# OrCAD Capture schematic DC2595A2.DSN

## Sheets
1 PAGE1: size Custom; title: HIGH VOLTAGE DUAL STEP-DOWN DC/DC CONVERTER; rev: 2; company: TM; note: DC/DC CONVERTER with POWER SYSTEM MANAGEMENT
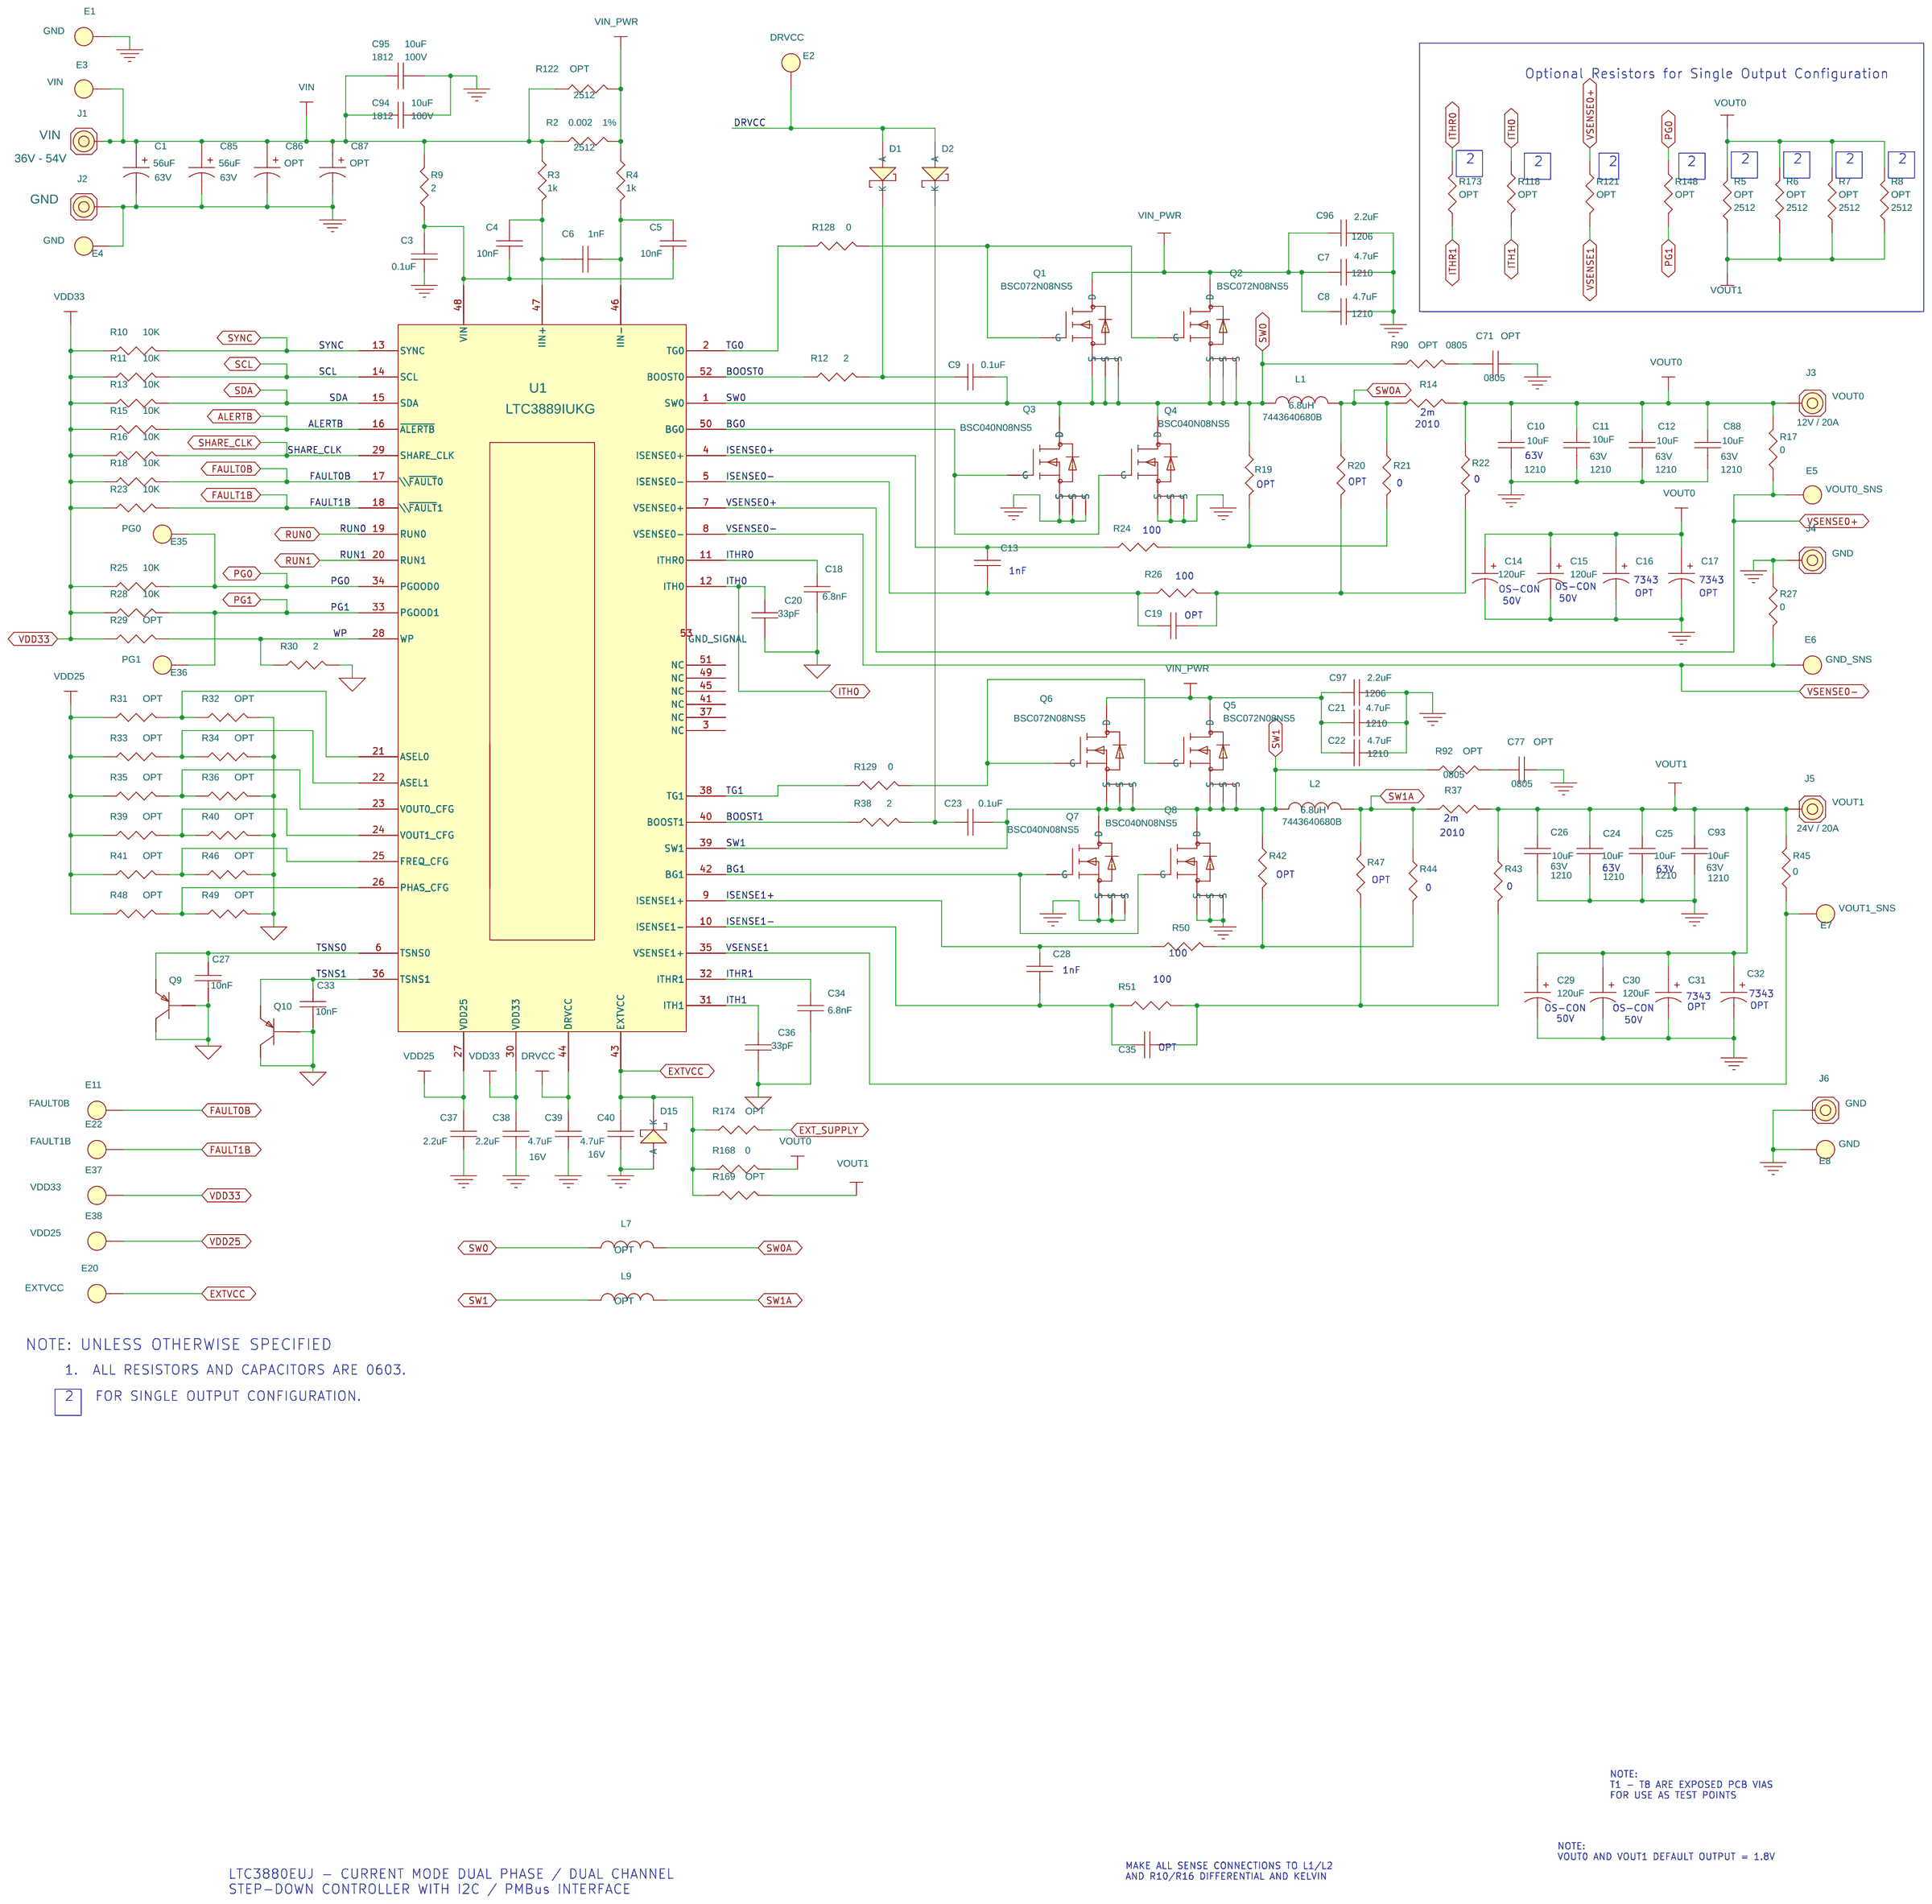
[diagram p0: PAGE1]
2 PAGE2: size Custom; note: WITH POWER SYSTEM MANAGEMENT
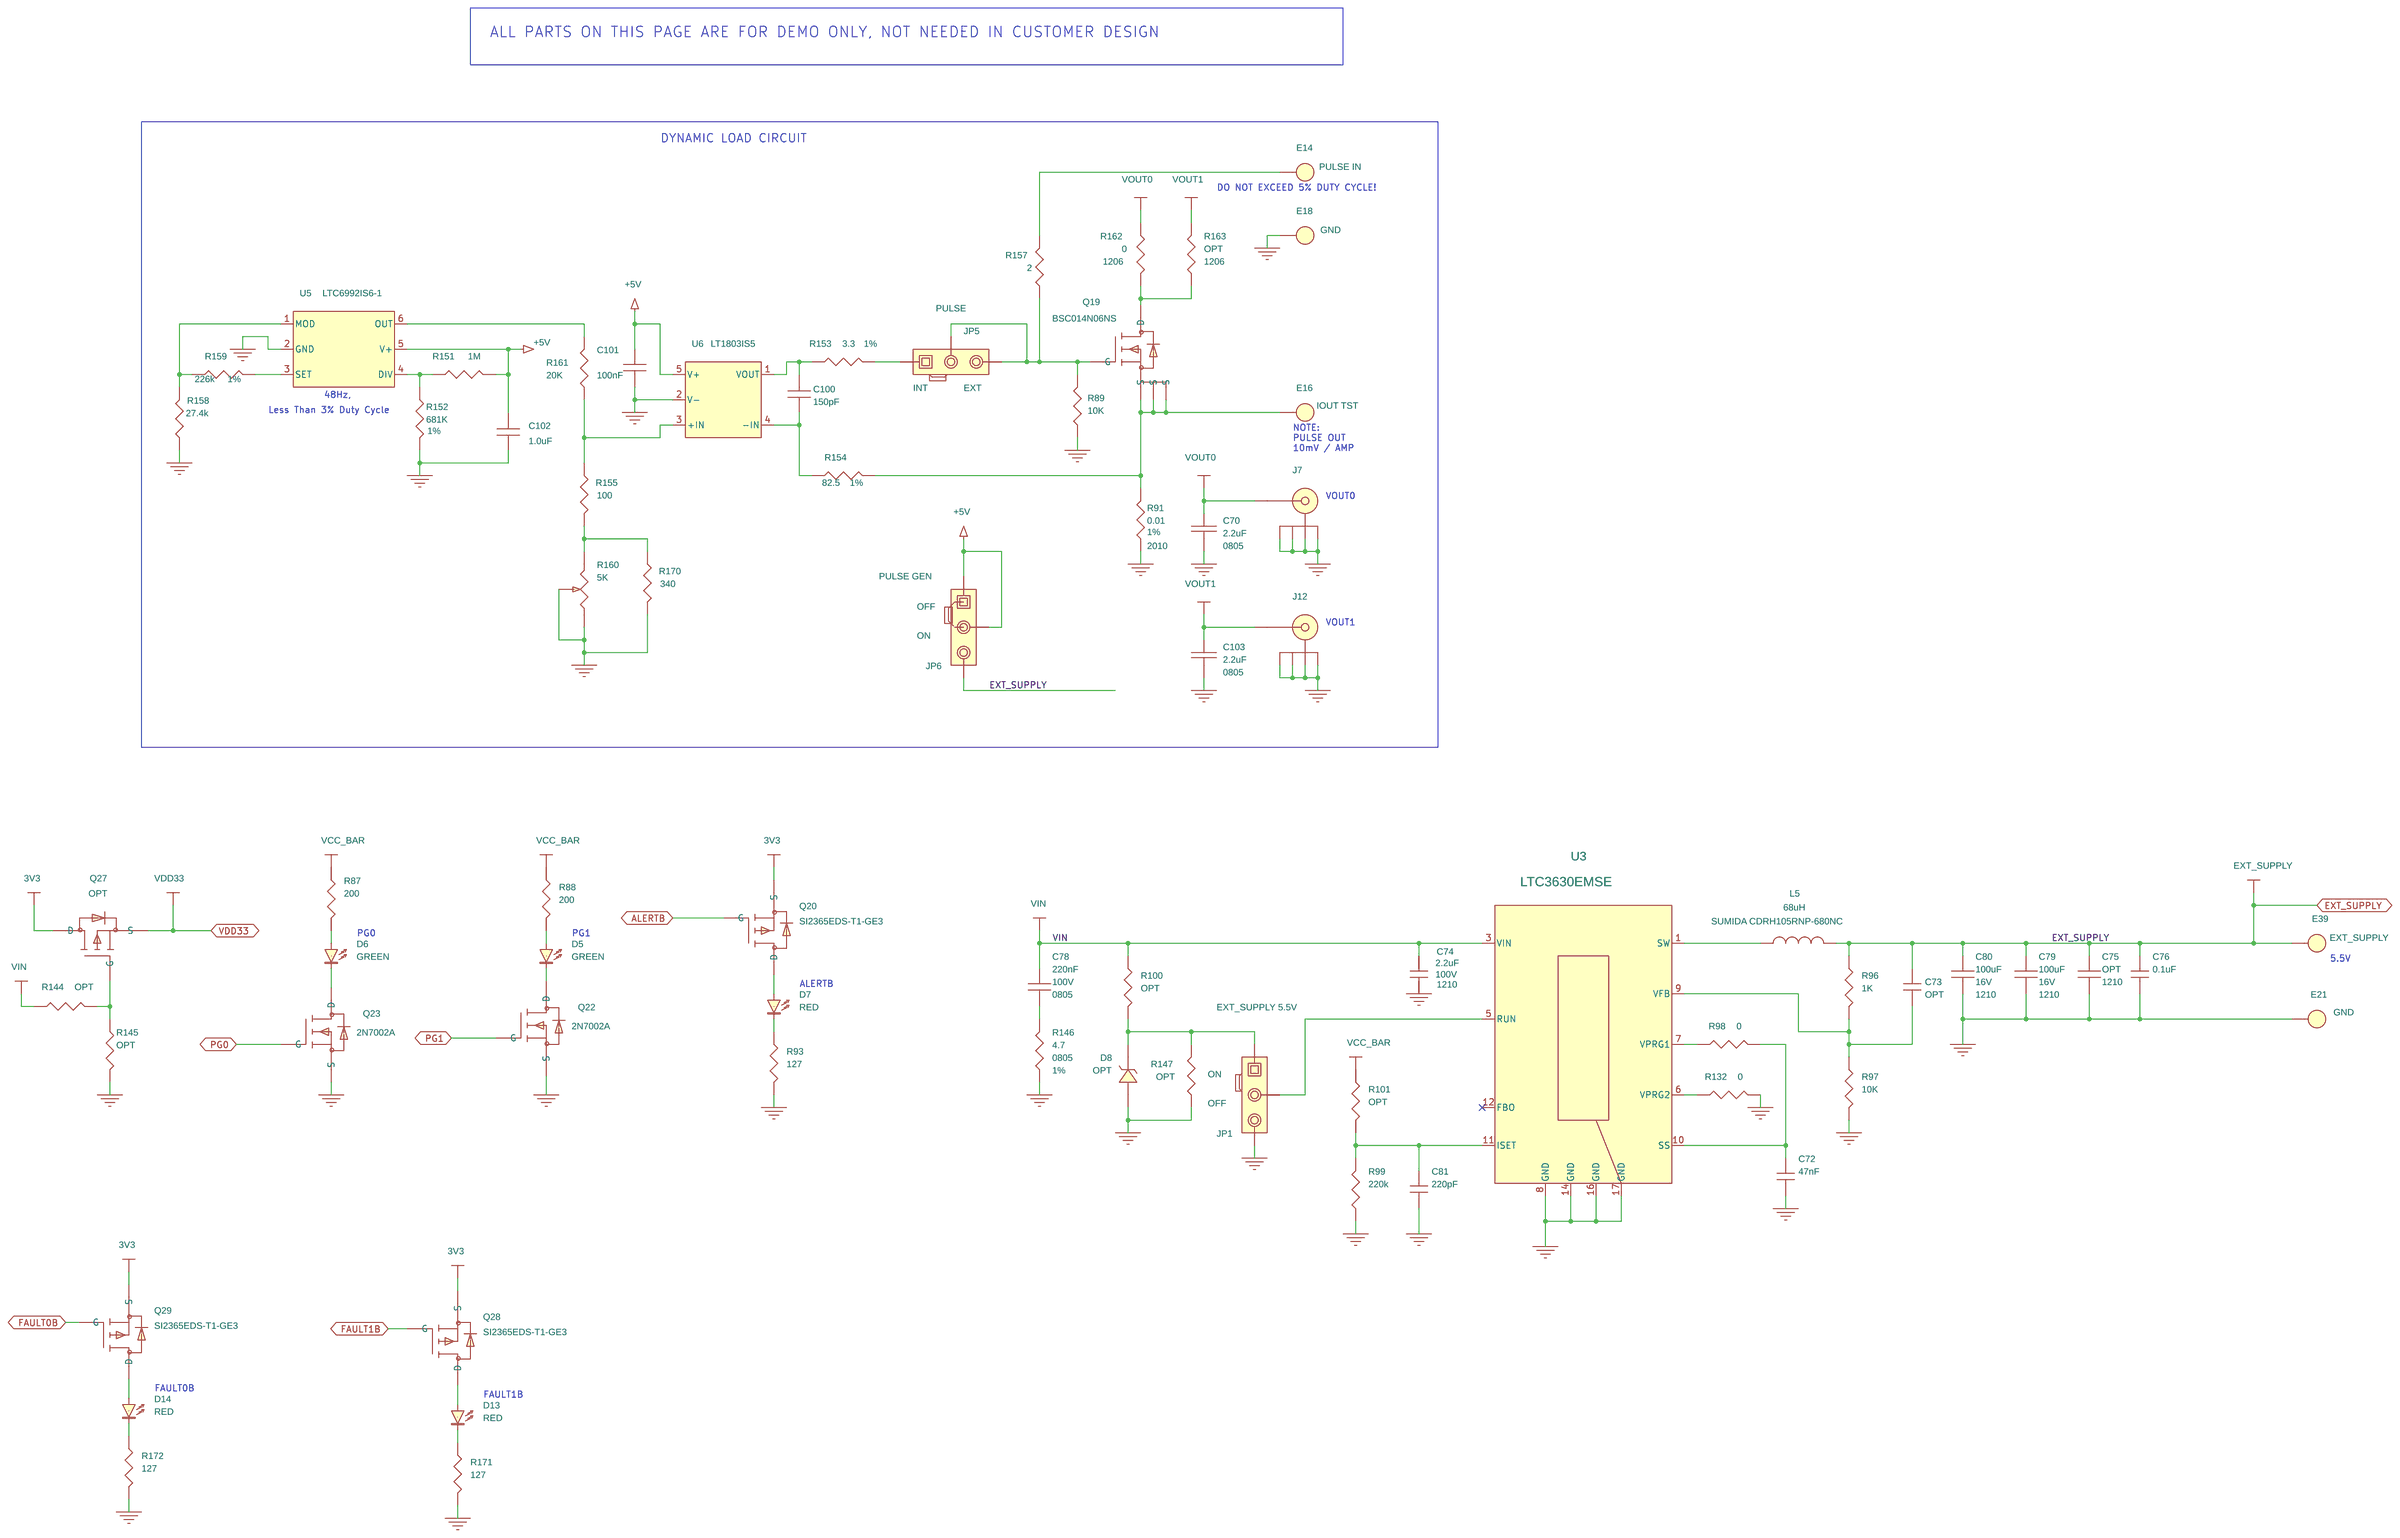
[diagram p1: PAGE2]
3 PAGE3: size B; note: WITH POWER SYSTEM MANAGEMENT
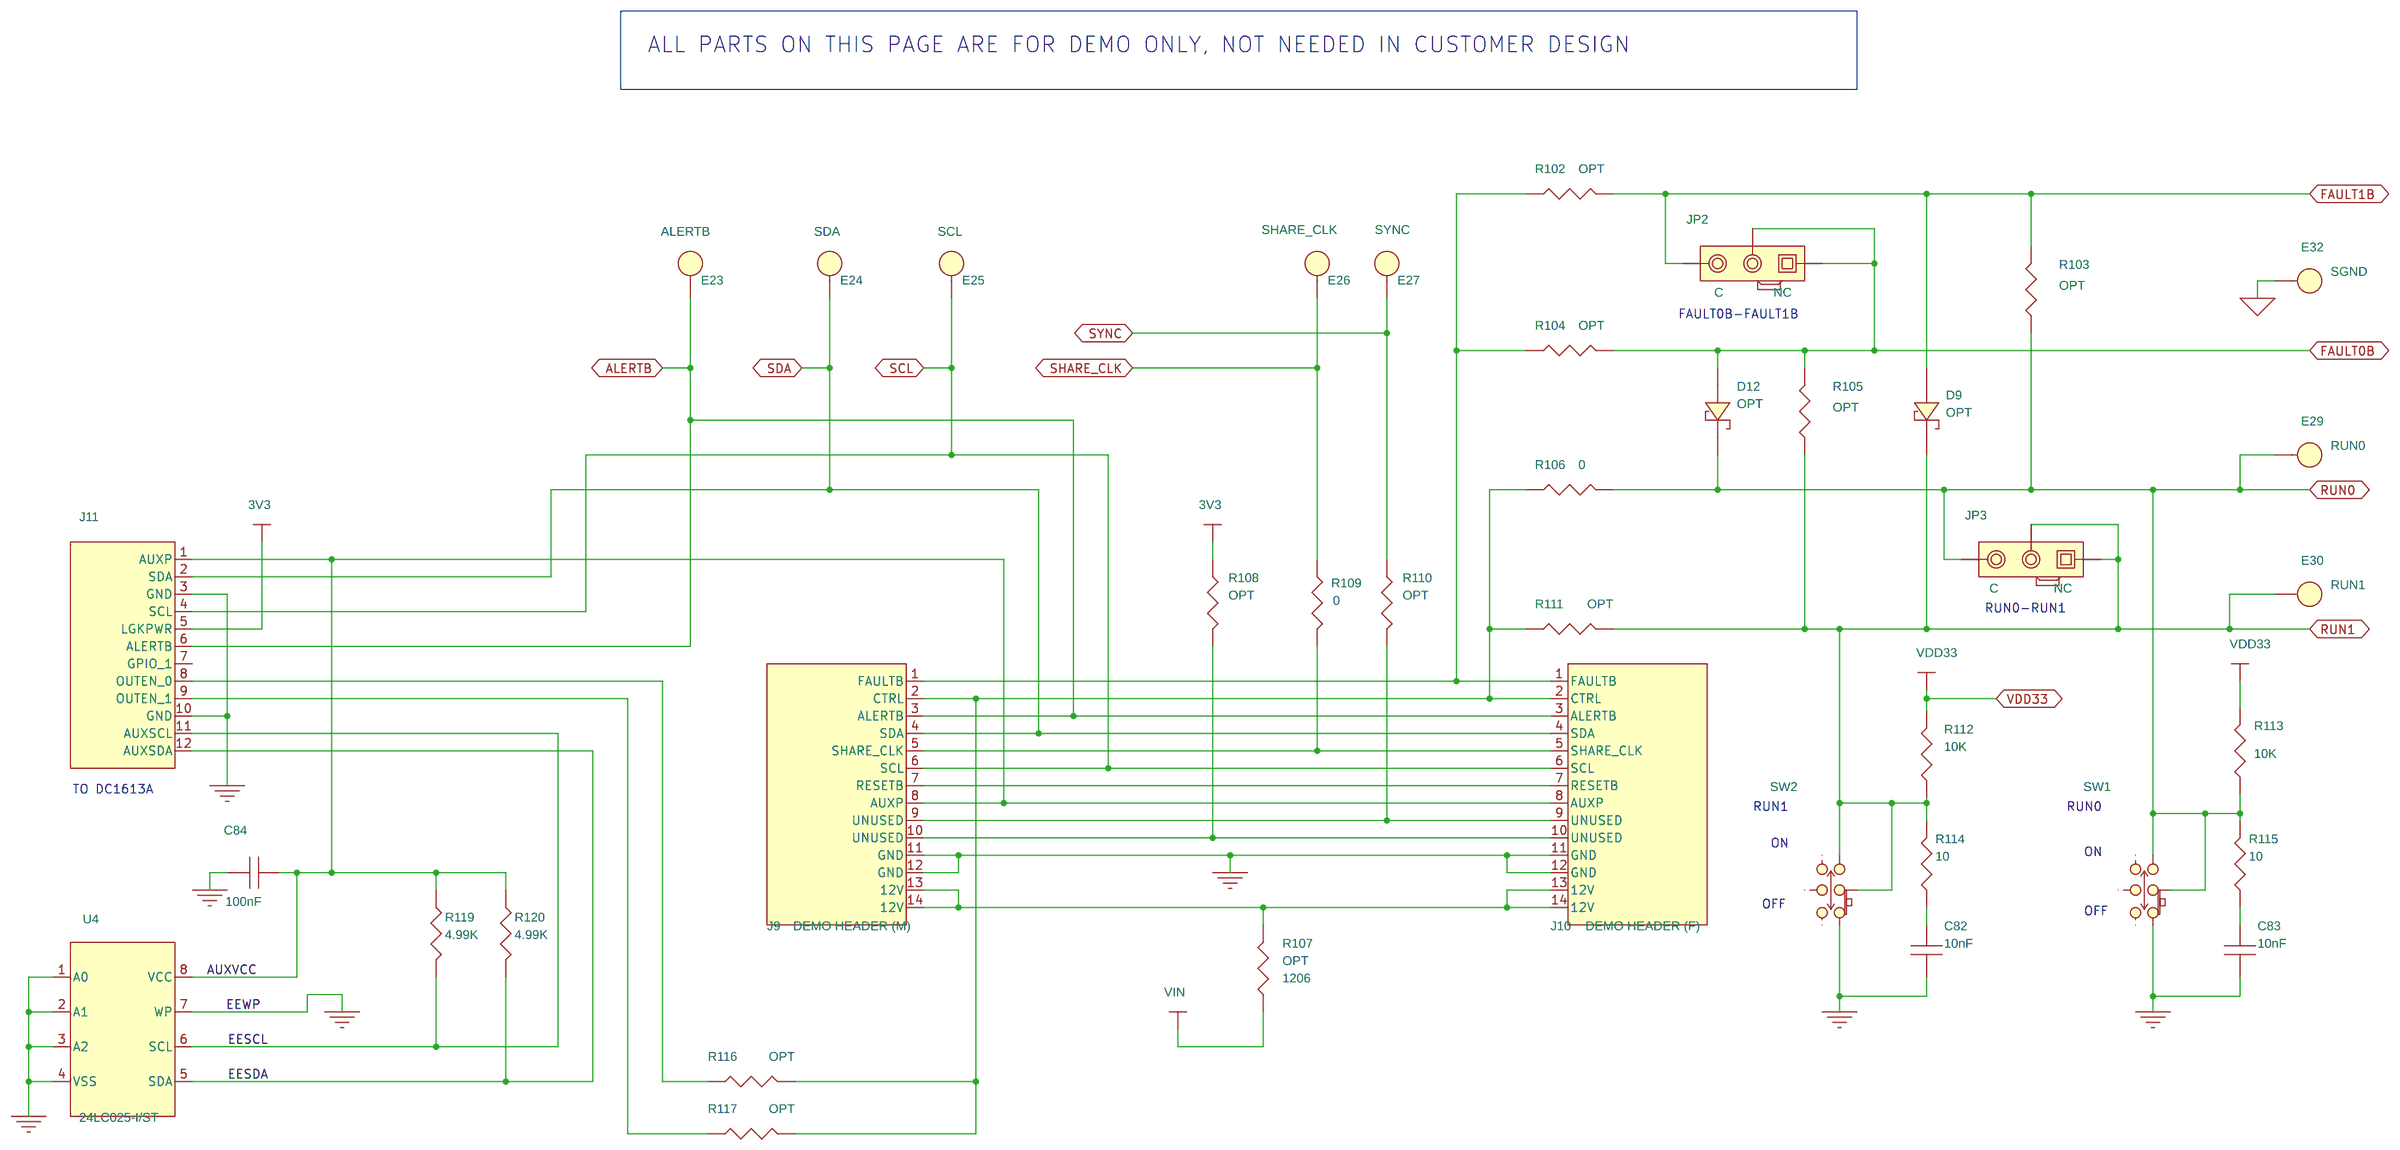
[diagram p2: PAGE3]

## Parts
sheet PAGE1
C1  56uF  [CAP\SUNCON\10X12.5]
C3  0.1uF  [0603]
C4  10nF  [0603]
C5  10nF  [0603]
C6  1nF  [0603]
C7  4.7uF  [1210]
C8  4.7uF  [1210]
C9  0.1uF  [0603]
C10  10uF  [1210]
C11  10uF  [1210]
C12  10uF  [1210]
C13  1nF  [0603]
C14  120uF  [CAP\SANYO\SVP\F8\10.3X10.3]
C15  120uF  [CAP\SANYO\SVP\F8\10.3X10.3]
C16  330uF  [7343]
C17  330uF  [7343]
C18  6.8nF  [0603]
C19  OPT  1.0uF  [0603]
C20  33pF  [0603]
C21  4.7uF  [1210]
C22  4.7uF  [1210]
C23  0.1uF  [0603]
C24  10uF  [1210]
C25  10uF  [1210]
C26  10uF  [1210]
C27  10nF  [0603]
C28  1nF  [0603]
C29  120uF  [CAP\SANYO\SVP\F8\10.3X10.3]
C30  120uF  [CAP\SANYO\SVP\F8\10.3X10.3]
C31  330uF  [7343]
C32  330uF  [7343]
C33  10nF  [0603]
C34  6.8nF  [0603]
C35  OPT 1.0uF  [0603]
C36  33pF  [0603]
C37  2.2uF  [0603]
C38  2.2uF  [0603]
C39  4.7uF  [0603]
C40  4.7uF  [0603]
C71  OPT  [0805]
C77  OPT  [0805]
C85  56uF  [CAP\SUNCON\10X12.5]
C86  OPT  [CAP\SANYO\10X10.2\CE]
C87  OPT  [CAP\SANYO\10X10.2\CE]
C88  10uF  [1210]
C93  10uF  [1210]
C94  10uF  [1812]
C95  10uF  [1812]
C96  2.2uF  [1206]
C97  2.2uF  [1206]
D1  DFLS1100-7  [POWERDI_123]
D2  DFLS1100-7  [POWERDI_123]
D15  DFLS1100-7  [POWERDI_123]
E1  PAD150-094  [PAD150-094]
E2  PAD150-094  [PAD150-094]
E3  PAD150-094  [PAD150-094]
E4  PAD150-094  [PAD150-094]
E5  PAD150-094  [PAD150-094]
E6  PAD150-094  [PAD150-094]
E7  PAD150-094  [PAD150-094]
E8  PAD150-094  [PAD150-094]
E11  PAD150-094  [PAD150-094]
E20  PAD150-094  [PAD150-094]
E22  PAD150-094  [PAD150-094]
E35  PAD150-094  [PAD150-094]
E36  PAD150-094  [PAD150-094]
E37  PAD150-094  [PAD150-094]
E38  PAD150-094  [PAD150-094]
J1  Testpin  [con\lug\10]
J2  Testpin  [con\lug\10]
J3  Testpin  [con\lug\10]
J4  Testpin  [con\lug\10]
J5  Testpin  [con\lug\10]
J6  Testpin  [con\lug\10]
L1  6.8uH  [IND\WURTH\7443630860]
L2  6.8uH  [IND\WURTH\7443630860]
L7  OPT  [IND\CLCRFT\SER2900]
L9  OPT  [IND\CLCRFT\SER2900]
Q1  BSC072N08NS5  [XSTR\INFINEON\PG-TDSON-8]
Q2  BSC072N08NS5  [XSTR\INFINEON\PG-TDSON-8]
Q3  BSC040N08NS5  [XSTR\INFINEON\PG-TDSON-8]
Q4  BSC040N08NS5  [XSTR\INFINEON\PG-TDSON-8]
Q5  BSC072N08NS5  [XSTR\INFINEON\PG-TDSON-8]
Q6  BSC072N08NS5  [XSTR\INFINEON\PG-TDSON-8]
Q7  BSC040N08NS5  [XSTR\INFINEON\PG-TDSON-8]
Q8  BSC040N08NS5  [XSTR\INFINEON\PG-TDSON-8]
Q9  MMBT3906LT1G  [SOT-323]
Q10  MMBT3906LT1G  [SOT-323]
R2  0.002  [2512]
R3  1k  [0603]
R4  1k  [0603]
R5  OPT  [2512]
R6  OPT  [2512]
R7  OPT  [2512]
R8  OPT  [2512]
R9  2  [0603]
R10  10K  [0603]
R11  10K  [0603]
R12  2  [0603]
R13  10K  [0603]
R14  0.003  [2010]
R15  10K  [0603]
R16  10K  [0603]
R17  0  [0603]
R18  10K  [0603]
R19  1.40K  [0603]
R20  0  [0603]
R21  0  [0603]
R22  0  [0603]
R23  10K  [0603]
R24  100  [0603]
R25  10K  [0603]
R26  100  [0603]
R27  0  [0603]
R28  10K  [0603]
R29  OPT  [0603]
R30  2  [0603]
R31  OPT  [0603]
R32  OPT  [0603]
R33  OPT  [0603]
R34  OPT  [0603]
R35  OPT  [0603]
R36  OPT  [0603]
R37  0.003  [2010]
R38  2  [0603]
R39  OPT  [0603]
R40  OPT  [0603]
R41  OPT  [0603]
R42  OPT 1.40K  [0603]
R43  0  [0603]
R44  0  [0603]
R45  0  [0603]
R46  OPT  [0603]
R47  OPT  0  [0603]
R48  OPT  [0603]
R49  OPT  [0603]
R50  100  [0603]
R51  100  [0603]
R90  OPT  [0805]
R92  OPT  [0805]
R118  OPT  [0603]
R121  OPT  [0603]
R122  OPT  [2512]
R128  0  [0603]
R129  0  [0603]
R148  OPT  [0603]
R168  0  [0603]
R169  OPT  [0603]
R173  OPT  [0603]
R174  OPT  [0603]
U1  LTC3889IUKG  [LT_UKG52(46)_7mmX8mm]
sheet PAGE2
C70  2.2uF  [0805]
C72  47nF  [0603]
C73  OPT  [0603]
C74  2.2uF  [1210]
C75  OPT  [1210]
C76  0.1uF  [0603]
C78  220nF  [0805]
C79  100uF  [1210]
C80  100uF  [1210]
C81  220pF  [0603]
C100  150pF  [0603]
C101  100nF  [0603]
C102  1.0uF  [0603]
C103  2.2uF  [0805]
D5  GREEN  [LED_0603]
D6  GREEN  [LED_0603]
D7  RED  [LED_0603]
D8  OPT  [SOD123]
D13  RED  [LED_0603]
D14  RED  [LED_0603]
E14  PAD150-094  [PAD150-094]
E16  PAD150-094  [PAD150-094]
E18  PAD150-094  [PAD150-094]
E21  PAD150-094  [PAD150-094]
E39  PAD150-094  [PAD150-094]
J7  XXX  [BNC5]
J12  XXX  [BNC5]
JP1  3 Pins 2mm Ctrs.  [SIP\3P\2MM]
JP5  3 Pins 2mm Ctrs.  [SIP\3P\2MM]
JP6  3 Pins 2mm Ctrs.  [SIP\3P\2MM]
L5  68uH  [IND\SUMIDA\CDRH105R\12X12]
Q19  BSC014N06NS  [LFPAK]
Q20  SI2365EDS-T1-GE3  [SOT23]
Q22  2N7002A  [SOT23]
Q23  2N7002A  [SOT23]
Q27  OPT  [SOT23]
Q28  SI2365EDS-T1-GE3  [SOT23]
Q29  SI2365EDS-T1-GE3  [SOT23]
R87  200  [0603]
R88  200  [0603]
R89  10K  [0603]
R91  0.01  [2010]
R93  127  [0603]
R96  1K  [0603]
R97  10K  [0603]
R98  0  [0603]
R99  220k  [0603]
R100  OPT  [0603]
R101  OPT  [0603]
R132  0  [0603]
R144  OPT  [0603]
R145  OPT  [0603]
R146  4.7  [0805]
R147  OPT  [0603]
R151  1M  [0603]
R152  681K  [0603]
R153  3.3  [0603]
R154  82.5  [0603]
R155  100  [0603]
R157  2  [0603]
R158  27.4k  [0603]
R159  226k  [0603]
R160  5K  [BOURNS_3386P]
R161  20K  [0603]
R162  0  [1206]
R163  OPT  [1206]
R170  340  [0603]
R171  127  [0603]
R172  127  [0603]
U3  LTC3630EMSE  [LT_MSE16_12]
U5  LTC6992IS6-1  [LT_S6]
U6  LT1803IS5  [LT_S5]
XJP1  2mm Ctrs.
XJP5  2mm Ctrs.
XJP6  2mm Ctrs.
sheet PAGE3
C82  10nF  [0603]
C83  10nF  [0603]
C84  100nF  [0603]
D9  OPT  [SOD-323]
D12  OPT  [SOD-323]
E23  ALERTB  [PAD150-094]
E24  SDA  [PAD150-094]
E25  SCL  [PAD150-094]
E26  SHARE_CLK  [PAD150-094]
E27  SYNC  [PAD150-094]
E29  RUN0  [PAD150-094]
E30  RUN1  [PAD150-094]
E32  SGND  [PAD150-094]
J9  DEMO HEADER (M)  [NPPN072FJFN]
J10  DEMO HEADER (F)  [NPPN072FJFN-RC]
J11  HD2X6-079  [HD2X6-079-MOLEX]
JP2  3 Pins 2mm Ctrs.  [SIP\3P\2MM]
JP3  3 Pins 2mm Ctrs.  [SIP\3P\2MM]
R102  OPT  [0603]
R103  OPT  [0603]
R104  OPT  [0603]
R105  OPT  [0603]
R106  0  [0603]
R107  OPT  [1206]
R108  OPT  [0603]
R109  0  [0603]
R110  OPT  [0603]
R111  OPT  [0603]
R112  10K  [0603]
R113  10K  [0603]
R114  10  [0603]
R115  10  [0603]
R116  OPT  [0603]
R117  OPT  [0603]
R119  4.99K  [0603]
R120  4.99K  [0603]
SW1  JP3X1/079\NO\12  [JS202011]
SW2  JP3X1/079\NO\12  [JS202011]
U4  24LC025-I/ST  [TSSOP-8_4.4MM]
XJP2  2mm Ctrs.
XJP3  2mm Ctrs.

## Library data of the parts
C1 C85 = CAP_POL: CAP, 56uF 20% 63V ELEC; Part Number: SUNCON 63HVP56M; VOLTAGE: 63V
C3 C9 C23 = CAP0603_1: CAP, 0603 0.1uF 10% 100V X7R; Component: cap; Manufacturer: TDK; Manufacturer P/N: C1608X7R1H104K; Part Number: MURATA GRM188R72A104KA35D; Tolerance: 10%; Type: cer 0603 X7R; Vendor: Digikey; Vendor P/N: 445-1314-1-ND
C4 C5 = CAP0603_1: CAP, 0603 10nF 10% 100V X7R; Component: cap; Manufacturer: TDK; Manufacturer P/N: C1608X7R1H104K; Part Number: MURATA GRM188R72A103KA01D; Tolerance: 10%; Type: cer 0603 X7R; Vendor: Digikey; Vendor P/N: 445-1314-1-ND
C6 = CAP0603_1: CAP, 0603 1nF 10% 100V X7R; Component: cap; Manufacturer: TDK; Manufacturer P/N: C1608X7R1H104K; Part Number: AVX 06031C102KAT2A; Tolerance: 10%; Type: cer 0603 X7R; Vendor: Digikey; Vendor P/N: 445-1314-1-ND; Volts/Amps/Watts: 50V
C7 C21 C22 = CAP1210_1: CAP, 1210 2.2uF 10% 100V X7R; Component: cap; Part Number: MURATA GRM32ER72A225KA35L; Part Type: CAP1812; Tolerance: 10%; Type: cer 1210; Vendor: Digikey; Vendor P/N: 587-1439-1-ND; Volts/Amps/Watts: 100V
C8 = CAP1210_1: CAP, 1210 2.2uF 10% 100V X7R; Component: cap; Part Number: MURATA GRM32ER72A225KA35L; Tolerance: 10%; Type: cer 1210; Vendor: Digikey; Vendor P/N: 587-1439-1-ND; Volts/Amps/Watts: 100V
C10 C25 C26 = CAP0603_1: CAP, 1210 10uF 20% 35V X5R; Component: cap; Manufacturer: Taiyo Yuden; Manufacturer P/N: GMJ325KB7106KMHT; Part Number: GMJ325KB7106KMHT; Part Type: CAP1210; Tolerance: 20%; Type: cer 1210 X5R; Vendor: Digikey; Vendor P/N: 445-1437-1-ND; Volts/Amps/Watts: 16V
C11 C12 C24 C88 C93 = CAP0603_1: CAP, 1210 10uF 20% 35V X5R; Component: cap; Manufacturer: Taiyo Yuden; Manufacturer P/N: GMJ325KB7106KMHT; Part Number: GMJ325KB7106KMHT; Part Type: CAP1210; Tolerance: 20%; Type: cer 1210 X5R; Vendor: Digikey; Vendor P/N: 445-1437-1-ND; Volts/Amps/Watts: 63V
C13 C28 = CAP0603_1: CAP, 0603 1nF 10% 16V X7R; Component: cap; Manufacturer: AVX; Manufacturer P/N: 06035C102KAT2A; Part Number: AVX 0603YC102KAT2A; Tolerance: 10%; Type: cer 0603 X7R; Vendor: Digikey; Vendor P/N: 478-1215-1-ND; Volts/Amps/Watts: 50V
C14 C29 C30 = CAPR12X5_0: CAP, 150uF 16V ELEC. OS-CON; Component: cap; Manufacturer: SANYO; Manufacturer P/N: 6TPF330M9L; Part Number: PANASONIC 35SVPF120M; Tolerance: 20%; Type: TANT; Volts/Amps/Watts: 6.3V
C15 = CAPR12X5_0: CAP, 150uF 16V ELEC. OS-CON; Component: cap; Manufacturer: SANYO; Manufacturer P/N: 6TPF330M9L; Part Number: PANASONIC 35SVPF120M; Part Type: CAP7343-43; Tolerance: 20%; Type: TANT; Volts/Amps/Watts: 6.3V
C16 C17 C31 C32 = CAPR12X5_0: CAP, 7343 OPTION; Component: cap; Manufacturer: SANYO; Manufacturer P/N: 6TPF330M9L; Part Number: OPTION; Tolerance: 20%; Type: TANT; Volts/Amps/Watts: 6.3V
C18 C34 = CAP0603_1: CAP, 0603 4.7nF 10% 50V X7R; Component: cap; Manufacturer: TDK; Manufacturer P/N: C1608C0G1H102J; Part Number: AVX 06035C472KAT2A; Tolerance: 5%; Type: cer 0603; Vendor: Digikey; Vendor P/N: 445-1293-1-ND; Volts/Amps/Watts: 50V
C19 C35 = CAP0603_1: CAP, 0603 OPTION; Manufacturer: Taiyo Yuden; Manufacturer P/N: EMK107B7105KA-T; Part Number: OPTION; Type: cer 0603 X7R; Vendor: Digikey; Vendor P/N: 587-1241-1-ND; Volts/Amps/Watts: 16V
C20 C36 = CAP0603_1: CAP, 0603 100pF 5% 50V C0G; Component: cap; Manufacturer: TDK; Manufacturer P/N: C1608C0G1H101J; Part Number: AVX 06035A101JAT2A; Tolerance: 5%; Type: cer 0603; Vendor: Digikey; Vendor P/N: 445-1281-1-ND
C27 C33 = CAP0603_1: CAP, 0603 10nF 10% 100V X7R; Component: cap; Manufacturer: TDK; Manufacturer P/N: C1608X7R1H103K; Part Number: MURATA GRM188R72A103KA01D; Tolerance: 10%; Type: cer 0603; Vendor: Digikey; Vendor P/N: 445-1311-1-ND; Volts/Amps/Watts: 50V
C37 C38 = CAP0603_1: CAP, 0603 2.2uF 10% 16V X5R; Component: cap; Manufacturer: TDK; Manufacturer P/N: C1608X7R1H104K; Part Number: AVX 0603YD225KAT2A; Tolerance: 10%; Type: cer 0603 X7R; Vendor: Digikey; Vendor P/N: 445-1314-1-ND; Volts/Amps/Watts: 50V
C39 = CAP0603_1: CAP, 0603 4.7uF 10% 16V X5R; Component: cap; Manufacturer: TDK; Manufacturer P/N: C1608X7R1H104K; Part Number: AVX 0603ZD475KAT2A; Tolerance: 10%; Type: cer 0603 X7R; Vendor: Digikey; Vendor P/N: 445-1314-1-ND; Volts/Amps/Watts: 16V
C40 = CAP0603_1: CAP, 0603 4.7uF 10% 16V X5R; Component: cap; Manufacturer: TDK; Manufacturer P/N: C1608X7R1H104K; Part Number: MURATA GRM188R61C475KAAJD; Tolerance: 10%; Type: cer 0603 X7R; Vendor: Digikey; Vendor P/N: 445-1314-1-ND; Volts/Amps/Watts: 16V
C71 C77 = CAP0603_1: CAP, 0805 OPTION; Component: cap; Manufacturer: TDK; Manufacturer P/N: C1608X7R1H104K; Part Number: OPTION; Tolerance: 10%; Type: cer 0603 X7R; Vendor: Digikey; Vendor P/N: 445-1314-1-ND; Volts/Amps/Watts: 50V
C86 C87 = CAP_POL: CAP, ELEC OPTION; Part Number: OPTION; VOLTAGE: 63V
C94 C95 = CAP1210_1: CAP, 1812 10uF 20% 100V X7S; Component: cap; Manufacturer: Taiyo Yuden; Manufacturer P/N: GMK325BJ106KN-T; Part Number: TDK CKG45NX7S2A106M500JH; Tolerance: 10%; Type: cer 1210; Vendor: Digikey; Vendor P/N: 587-1439-1-ND; Volts/Amps/Watts: 100V
C96 C97 = CAP0603_1: CAP, 1206 2.2uF 10% 100V X7R; Component: cap; Manufacturer: TDK; Manufacturer P/N: C1608X7R1H104K; Part Number: MURATA GRM31CR72A225KA73L; Tolerance: 10%; Type: cer 0603 X7R; Vendor: Digikey; Vendor P/N: 445-1314-1-ND; Volts/Amps/Watts: 100V
D1 D15 = cmdsh-3_1: DIODE, SCHOTTKY 100V, 1A; Component: diode; Manufacturer: Central; Manufacturer P/N: CMDSH-3TR; Part Number: DIODES/ZETEX, DFLS1100-7; Type: Schottky; Vendor: Mouser; Vendor P/N: 610-CMDSH-3; Volts/Amps/Watts: 30V 100mA
D2 = cmdsh-3_2: DIODE, SCHOTTKY 100V, 1A; Component: diode; Manufacturer: Central; Manufacturer P/N: CMDSH-3TR; Part Number: DIODES/ZETEX, DFLS1100-7; Type: Schottky; Vendor: Mouser; Vendor P/N: 610-CMDSH-3; Volts/Amps/Watts: 30V 100mA
E1 E4 E8 E18 = E: TURRET; 10th Part Field: 3.3V / 3A; 9th Part Field: GND; Part Number: MILL-MAX 2501-2-00-80-00-00-07-0
E2 = E: TURRET; 10th Part Field: 3.3V / 3A; 9th Part Field: DRVCC; Part Number: MILL-MAX 2501-2-00-80-00-00-07-0
E3 = E: TURRET; 10th Part Field: 3.3V / 3A; 9th Part Field: VIN; Part Number: MILL-MAX 2501-2-00-80-00-00-07-0
E5 = E: TURRET; 10th Part Field: 3.3V / 3A; 9th Part Field: VOUT0_SNS; Part Number: MILL-MAX 2501-2-00-80-00-00-07-0
E6 = E: TURRET; 10th Part Field: 3.3V / 3A; 9th Part Field: GND_SNS; Part Number: MILL-MAX 2501-2-00-80-00-00-07-0
E7 = E: TURRET; 10th Part Field: 3.3V / 3A; 9th Part Field: VOUT1_SNS; Part Number: MILL-MAX 2501-2-00-80-00-00-07-0
E11 = E: TURRET; 10th Part Field: 3.3V / 3A; 9th Part Field: FAULT0B; Part Number: MILL-MAX 2501-2-00-80-00-00-07-0
E20 = E: TURRET; 10th Part Field: 3.3V / 3A; 9th Part Field: EXTVCC; Part Number: MILL-MAX 2501-2-00-80-00-00-07-0
E22 = E: TURRET; 10th Part Field: 3.3V / 3A; 9th Part Field: FAULT1B; Part Number: MILL-MAX 2501-2-00-80-00-00-07-0
E35 = E: TURRET; 10th Part Field: 3.3V / 3A; 9th Part Field: PG0; Part Number: MILL-MAX 2501-2-00-80-00-00-07-0
E36 = E: TURRET; 10th Part Field: 3.3V / 3A; 9th Part Field: PG1; Part Number: MILL-MAX 2501-2-00-80-00-00-07-0
E37 = E: TURRET; 10th Part Field: 3.3V / 3A; 9th Part Field: VDD33; Part Number: MILL-MAX 2501-2-00-80-00-00-07-0
E38 = E: TURRET; 10th Part Field: 3.3V / 3A; 9th Part Field: VDD25; Part Number: MILL-MAX 2501-2-00-80-00-00-07-0
J1 = PEM-kfh-032-10: STUD, TESTPIN; 10th Part Field: 36V - 54V; 9th Part Field: VIN; Part Number: PEM KFH-032-10
J2 = PEM-kfh-032-10: STUD, TESTPIN; 10th Part Field: 5 - 24V #; 9th Part Field: GND; Part Number: PEM KFH-032-10
J3 = PEM-kfh-032-10: STUD, TESTPIN; 10th Part Field: 12V / 20A; 9th Part Field: VOUT0; Part Number: PEM KFH-032-10
J4 J6 = PEM-kfh-032-10: STUD, TESTPIN; 10th Part Field: 12V, MAX 10A; 9th Part Field: GND; Part Number: PEM KFH-032-10
J5 = PEM-kfh-032-10: STUD, TESTPIN; 10th Part Field: 24V / 20A; 9th Part Field: VOUT1; Part Number: PEM KFH-032-10
L1 = IND-RLF7030-OPT_1: IND, 8.6uH; Component: ind; Label: <label>; Manufacturer: VITECH; Manufacturer P/N: 7443640680B; Part Number: WURTH ELEKTRONIK 7443630860; Vendor: LTC; Vendor P/N: 59PR9875N; Volts/Amps/Watts: 20A
L2 = IND-RLF7030-OPT_0: IND, 8.6uH; Component: ind; Label: <label>; Manufacturer: VITECH; Manufacturer P/N: 7443640680B; Part Number: WURTH ELEKTRONIK 7443630860; Vendor: LTC; Vendor P/N: 59PR9875N; Volts/Amps/Watts: 20A
L7 L9 = IND-RLF7030-OPT_1: IND, 6.8uH OPTION; Component: ind; Label: <label>; Manufacturer: VITECH; Manufacturer P/N: 59PR9875N; Part Number: COILCRAFT SER2915H-682KL/SER2918H-682KL OPTION; Vendor: LTC; Vendor P/N: 59PR9875N; Volts/Amps/Watts: 20A
Q1 Q6 = MOS_FET_6: XSTR, MOSFET N-CH 60V 25A 5 PIN LFPAK; Part Number: RENESAS RJK0651DPB
Q2 Q4 Q5 Q8 = MOS_FET_6: XSTR, OPTION; Part Number: OPTION
Q3 Q7 = MOS_FET_6: XSTR, MOSFET N-CH 60V 45A 5 PIN LFPAK; Part Number: RENESAS RJK0653DPB
Q9 Q10 = MMBT3906LT1_0: XSTR, PNP GENERAL PURPOSE SOT-323; Component: trans; Part Number: DIODES INC. MMST3906-7-F; Part Type: MMBT3906LT1; Vendor P/N: MMBT3906LT1GOSCT-ND
R2 R122 = RES2512_0: RES, 2512 0.006 OHMS 1% 1W; Component: res; Manufacturer: Panasonic; Part Number: PANASONIC ERJ-M1WSF6MU; Tolerance: 1%; Volts/Amps/watts: 1W
R3 R4 = RES0603_9: RES, 0603 1k OHMS 5% 1/10W; Manufacturer: Rohm; Manufacturer P/N: MCR03EZPFX2201; Part Number: VISHAY CRCW06031K00JNEA; Vendor: Digikey; Vendor P/N: RHM2.20KHCT-ND; Volts/Amps/Watts: 0.1W
R5-R7 = RES0603_5: RES, 2512 0 OHM JUMPER OPTION; Label: 1W; Manufacturer: VISHAY; Manufacturer P/N: CRCW251230R0JNEG; Part Number: RN5326 2512 TEPRO NAKOMA OPTION; Tolerance: 5%; Vendor: Digikey; Vendor P/N: 541-30XCT-ND; Volts/Amps/Watts: 0.1W
R8 = RES0603_5: RES, 2512 0 OHM JUMPER OPTION; Label: 1W; Manufacturer: VISHAY; Manufacturer P/N: CRCW251230R0JNEG; Part Number: RN5326 2512 TEPRO NAKOMA OPTION; Tolerance: 5%; Vendor: Digikey; Vendor P/N: 541-30XCT-ND; Volts/Amps/Watts: 1W
R9 = RES0603_9: RES, 0603 2 OHMS 5% 1/10W; Manufacturer: Rohm; Manufacturer P/N: RHM0.0GCT-ND; Part Number: VISHAY CRCW06032R00JNEA; Vendor: Digikey; Vendor P/N: RHM0.0GCT-ND; Volts/Amps/Watts: 0.1W
R10 R11 R13 R15 R16 R18 R23 R25 R28 R112 R113 = RES0603_9: RES, 0603 10k OHMS 5% 1/10W; Manufacturer: Panasonic; Manufacturer P/N: ERJ-3EKF1000V; Part Number: VISHAY CRCW060310K0JNEA; Part Type: CR0402; Vendor: Digikey; Vendor P/N: P100HCT-ND; Volts/Amps/Watts: 0.1W
R12 R30 R38 = RES0603_9: RES, 0603 2 OHMS 5% 1/10W; Manufacturer: Panasonic; Manufacturer P/N: ERJ-3EKF1000V; Part Number: VISHAY CRCW06032R00JNEA; Part Type: CR0402; Vendor: Digikey; Vendor P/N: P100HCT-ND; Volts/Amps/Watts: 0.1W
R14 = RES2512_0: RES, 2010 3m OHMS 1% 1/2W; Component: res; Manufacturer: Panasonic; Manufacturer P/N: ERJ-M1WSF8M0U; Part Number: VISHAY WSL20103L000FEA; Tolerance: 1%; Vendor: Digikey; Vendor P/N: ERJ-M1WTF2M0U; Volts/Amps/watts: 1W
R17 = RES0603_9: RES, 0603 0 OHMS JUMPER; Manufacturer: Rohm; Manufacturer P/N: MCR03EZPFX1000; Part Number: VISHAY CRCW06030000Z0EA; Vendor: Digikey; Vendor P/N: RHM100HCT-ND; Volts/Amps/Watts: 0.1W
R19 R42 = RES0603_9: RES, 0603 OPTION; Manufacturer: Rohm; Manufacturer P/N: MCR03EZPFX2201; Part Number: OPTION; Vendor: Digikey; Vendor P/N: RHM2.20KHCT-ND; Volts/Amps/Watts: 0.1W
R20 = RES0603_9: RES, 0603 OPTION; Manufacturer: Rohm; Manufacturer P/N: RHM0.0GCT-ND; Part Number: OPTION; Tolerance: 5%; Vendor: Digikey; Vendor P/N: RHM0.0GCT-ND; Volts/Amps/Watts: 0.1W
R21 R22 R43 R44 R128 R129 = RES0603_9: RES, 0603 0 OHMS JUMPER; Manufacturer: Rohm; Manufacturer P/N: MCR03EZPFX2201; Part Number: VISHAY CRCW06030000Z0EA; Vendor: Digikey; Vendor P/N: RHM2.20KHCT-ND; Volts/Amps/Watts: 0.1W
R24 R26 = RES0603_9: RES, 0603 100 OHMS 5% 1/10W; Manufacturer: Panasonic; Manufacturer P/N: ERJ-3EKF1000V; Part Number: VISHAY CRCW0603100RJNEA; Vendor: Digikey; Vendor P/N: P100HCT-ND; Volts/Amps/Watts: 0.1W
R27 = RES0603_9: RES, 0603 0 OHMS JUMPER; Manufacturer: Yageo; Manufacturer P/N: RC0603JR-070RL; Part Number: VISHAY CRCW06030000Z0EA; Tolerance: 5%; Vendor: Digikey; Vendor P/N: 311-0.0GRCT-ND; Volts/Amps/Watts: 0.1W
R29 R31-R36 R39-R41 R46 R48 R49 R169 = RES0603_9: RES, 0603 OPTION; Manufacturer: Panasonic; Manufacturer P/N: ERJ-3EKF1000V; Part Number: OPTION; Part Type: CR0402; Vendor: Digikey; Vendor P/N: P100HCT-ND; Volts/Amps/Watts: 0.1W
R37 = RES2512_0: RES, 2010 3m OHMS 1% 1/2W; Component: res; Manufacturer: Panasonic; Manufacturer P/N: ERJ-M1WSF8M0U; Part Number: VISHAY WSL20103L000FEA; Part Type: RES2512; Tolerance: 1%; Vendor: Digikey; Vendor P/N: ERJ-M1WTF2M0U; Volts/Amps/watts: 1W
R45 = RES0603_9: RES, 0603 0 OHMS JUMPER; Manufacturer: Rohm; Manufacturer P/N: RHM0.0GCT-ND; Part Number: VISHAY CRCW06030000Z0EA; Tolerance: 5%; Vendor: Digikey; Vendor P/N: RHM0.0GCT-ND; Volts/Amps/Watts: 0.1W
R47 = RES0603_8: RES, 0603 OPTION; Manufacturer: Rohm; Manufacturer P/N: RHM0.0GCT-ND; Part Number: OPTION; Tolerance: 5%; Vendor: Digikey; Vendor P/N: RHM0.0GCT-ND; Volts/Amps/Watts: 0.1W
R50 R51 = RES0603_9: RES, 0603 100 OHMS 5% 1/10W; Component: res; Manufacturer: Panasonic; Manufacturer P/N: ERJ-3EKF1000V; Part Number: VISHAY CRCW0603100RJNEA; Tolerance: 1%; Vendor: Digikey; Vendor P/N: P100HCT-ND; Volts/Amps/Watts: 0.1W
R90 R92 = RES0603_9: RES, 0805 OPTION; Label: OPT 0; Manufacturer: Rohm; Manufacturer P/N: RHM0.0GCT-ND; Part Number: OPTION; Vendor: Digikey
R118 R121 R148 R173 = RES0603_9: RES, 0603 OPTION; Label: 0; Manufacturer: Rohm; Manufacturer P/N: MCR03EZPFX2201; Part Number: OPTION; Vendor: Digikey; Vendor P/N: RHM2.20KHCT-ND; Volts/Amps/Watts: 0.1W
R168 = RES0603_9: RES, 0603 0 OHMS JUMPER; Manufacturer: Panasonic; Manufacturer P/N: ERJ-3EKF1000V; Part Number: VISHAY CRCW06030000Z0EA; Part Type: CR0402; Vendor: Digikey; Vendor P/N: P100HCT-ND; Volts/Amps/Watts: 0.1W
R98 R174 = RES0603_9: RES, 0603 0 OHMS JUMPER; Manufacturer: ROHM; Manufacturer P/N: MCR03EZPFX4991; Part Number: VISHAY CRCW06030000Z0EA; Volts/Amps/Watts: <Volts/Amps/Watts>
U1 = LTC3880-M0001_20: ASSY, IC, WIDE INPUT AND OUTPUT DC/DC CONVERTER; Component: IC; Manufacturer: LTC; Manufacturer P/N: LTC3886IUKG; Part Number: LINEAS TECH. LTC3886IUKG#10E2-1PBF-ES; Part Type: LTC3886IUKG; Vendor: LTC; Vendor P/N: LTC3880_M0001
C70 C103 = CAP1206_1: CAP, 0805 2.2uF 10% 16V X7R; Manufacturer: Kemet; Part Number: AVX 0805YC225KAT2A; Tolerance: 10%; Type: cer 1206 X7R; Vendor: Digikey; Vendor P/N: 399-4937-1-ND; Volts/Amps/Watts: 16V
C72 = CAP-NP: CAP, 0603 47nF 10% 25V X7R; Part Number: AVX 06033C473KAT2A
C73 = CAP-NP: CAP, 0603 OPTION; Part Number: OPTION
C74 = CAP-NP: CAP, 1210 2.2uF 10% 100V X7R; 1ST PART FIELD: 100V; Part Number: MURATA GRM32ER72A225KA35L
C75 = UMK325BJ105MH: CAP, 1210 OPTION; 1st Part Field: 10V; Part Number: OPTION
C76 = CAP-NP: CAP, 0603 0.1uF 10% 25V X7R; 1ST PART FIELD: 10V; Part Number: AVX 06033C104KAT2A
C78 = UMK325BJ105MH: CAP, 0805 220nF 10% 100V X7R; 1st Part Field: 100V; Part Number: MURATA GRM21AR72A224KAC5L
C79 C80 = UMK325BJ105MH: CAP, 1210 100uF 20% 10V X5R; 1st Part Field: 16V; Part Number: MURATA GRM32ER61A107ME20L
C81 = CAP-NP: CAP, 0603 220pF 10% 50V X7R; Part Number: AVX 06035C221KAT2A
C100 = CAP_NP: CAP, 0603 150pF 5% 50V NPO; Part Number: AVX 06035A151JAT2A
C84 C101 = CAP_NP: CAP, 0603 100nF 20% 16V X7R; Part Number: AVX 0603YC104MAT2A
C102 = CAP_NP: CAP, 0603 1uF 20% 25V X5R; Part Number: AVX 06033D105MAT2A
D5 D6 = DIODE-LED_2: LED, 0603 GREEN; Label: RED; Manufacturer: PANASONIC; Part Number: OSRAM LG L29K-G2J1-24-Z
D7 D13 D14 = DIODE-LED_2: LED, 0603 RED; Manufacturer: PANASONIC; Part Number: OSRAM LS L29K-H1J2-1-Z
D8 = DIODE_ZENER31_0: DIODE, ZENER OPTION; Part Number: OPTION
E14 = E: TURRET; 10th Part Field: 3.3V / 3A; 9th Part Field: PULSE IN; Part Number: MILL-MAX 2501-2-00-80-00-00-07-0
E16 = E: TURRET; 10th Part Field: 3.3V / 3A; 9th Part Field: IOUT TST; Part Number: MILL-MAX 2501-2-00-80-00-00-07-0
E21 = E: TURRET; 9th Part Field: GND; Part Number: MILL-MAX 2501-2-00-80-00-00-07-0
E39 = E: TURRET; 10th Part Field: 3.3V / 3A; 9th Part Field: EXT_SUPPLY; Part Number: MILL-MAX 2501-2-00-80-00-00-07-0
J7 J12 = BNC5-SCH_0: CONN, BNC,5 PINS; Part Number: CONNEX 112404
JP1 = Samtec_TMM-103-02-L-S_0: HEADER, 3 PIN 2mm; 10th Part Field: ITH; 11th Part Field: OFF; 12th Part Field: EXT_SUPPLY 5.5V; 9th Part Field: ON; Part Number: SULLINS NRPN031PAEN-RC
JP5 = Samtec_TMM-103-02-L-S_0: HEADER, 3 PIN 2mm; 10th Part Field: ITH; 11th Part Field: EXT; 12th Part Field: PULSE; 9th Part Field: INT; Part Number: SULLINS NRPN031PAEN-RC
JP6 = Samtec_TMM-103-02-L-S_0: HEADER, 3 PIN 2mm; 10th Part Field: ITH; 11th Part Field: ON; 12th Part Field: PULSE GEN; 9th Part Field: OFF; Part Number: SULLINS NRPN031PAEN-RC
L5 = IND: IND, 68uH; 5th Part Field: SUMIDA CDRH105RNP-680NC; Part Number: SUMIDA CDRH105RNP-680NC
Q19 = MOS_FET_6: XSTR, MOSFET N-CH 30V 30A 5 PIN LFPAK; Part Number: RENESAS RJK0305DPB-00#J0
Q20 Q28 Q29 = P-MOSFET: XSTR, MOSFET P-CH 20V 5.2A SOT-23; Part Number: VISHAY SI2365EDS-T1-GE3
Q22 = TRANSISTOR_1: XSTR, MOSFET N-CH 60V 115mA SOT23; Part Number: FAIRCHILD 2N7002A
Q23 = TRANSISTOR_0: XSTR, MOSFET N-CH 60V 115mA SOT23; Part Number: FAIRCHILD 2N7002A
Q27 = P-MOSFET: XSTR, N-CHANNEL DMOS FET OPTION; Part Number: OPTION
R87 R88 = RES0603_9: RES, 0603 200 OHMS 5% 1/10W; Label: OPT 0; Manufacturer: Rohm; Manufacturer P/N: RHM0.0GCT-ND; Part Number: VISHAY CRCW0603200RJNEA; Tolerance: 5%; Vendor: Digikey; Vendor P/N: RHM0.0GCT-ND; Volts/Amps/Watts: 0.1W
R89 = RES0603_9: RES, 0603 10k OHMS 5% 1/10W; Part Number: VISHAY CRCW060310K0JNEA
R91 = RES0603_5: RES, 2010 0.01 OHMS 1% 1/2W; Label: 1W; Manufacturer: VISHAY; Manufacturer P/N: CRCW251230R0JNEG; Part Number: VISHAY WSL2010R0100FEA; Tolerance: 1%; Vendor: Digikey; Vendor P/N: 541-30XCT-ND; Volts/Amps/Watts: 0.1W
R93 R171 R172 = RES0603_9: RES, 0603 127 OHMS 1% 1/10W; Label: OPT 0; Manufacturer: Rohm; Manufacturer P/N: RHM0.0GCT-ND; Part Number: VISHAY CRCW0603127RFKEA; Tolerance: 5%; Vendor: Digikey; Vendor P/N: RHM0.0GCT-ND; Volts/Amps/Watts: 0.1W
R96 = RES0603_9: RES, 0603 0 OHMS JUMPER; Manufacturer: ROHM; Manufacturer P/N: MCR03EZPFX4991; Part Number: VISHAY CRCW06030000Z0EA
R97 R100 R101 R147 = RES0603_9: RES, 0603 OPTION; Manufacturer: ROHM; Manufacturer P/N: MCR03EZPFX4991; Part Number: OPTION
R99 = RES0603_9: RES, 0603 220k OHMS 5% 1/10W; Manufacturer: ROHM; Manufacturer P/N: MCR03EZPFX4991; Part Number: VISHAY CRCW0603220KJNEA
R132 = RES0603_9: RES, 0603 0 OHMS JUMPER; Manufacturer: Rohm; Manufacturer P/N: MCR03EZPFX2201; Part Number: VISHAY CRCW06030000Z0EA
R144 R145 = RES0603_11: RES, 0603 OPTION; Part Number: OPTION
R146 = RES0603_9: RES, 0805 4.7 OHMS 1% 0.125W; Label: OPT 0; Manufacturer: Rohm; Manufacturer P/N: RHM0.0GCT-ND; Part Number: VISHAY CRCW08054R70FKEA; Tolerance: 1%; Vendor: Digikey
R151 = RES0603_0: RES, 0603 1M OHMS 5% 1/10W; Label: OPT 0; Manufacturer: Rohm; Manufacturer P/N: RHM0.0GCT-ND; Part Number: VISHAY CRCW06031M00JNEA; Vendor: Digikey
R152 = RES0603_0: RES, 0603 681K OHMS 1% 1/10W; Manufacturer: ROHM; Manufacturer P/N: MCR03EZPFX4991; Part Number: VISHAY CRCW0603681KFKEA; Tolerance: 1%
R153 = RES0603_0: RES, 0603 3.3 OHMS 1% 1/10W; Manufacturer: ROHM; Manufacturer P/N: MCR03EZPFX4991; Part Number: VISHAY CRCW06033R30FKEA; Tolerance: 1%; Vendor: Digikey
R154 = RES0603_0: RES, 0603 82.5 OHMS 1% 1/10W; Manufacturer: ROHM; Manufacturer P/N: MCR03EZPFX4991; Part Number: VISHAY CRCW060382R5FKEA; Tolerance: 1%; Vendor: Digikey
R155 = RES0603_0: RES, 0603 100 OHMS 5% 1/10W; Manufacturer: ROHM; Manufacturer P/N: MCR03EZPFX4991; Part Number: VISHAY CRCW0603100RJNEA; Vendor: Digikey; Vendor P/N: RHM4.99KHCT-ND; Volts/Amps/Watts: 0.1w
R157 = RES0603_0: RES, 0603 2 OHMS 5% 1/10W; Manufacturer: ROHM; Manufacturer P/N: MCR03EZPFX4991; Part Number: VISHAY CRCW06032R00JNEA; Vendor: Digikey; Vendor P/N: RHM4.99KHCT-ND; Volts/Amps/Watts: 0.1w
R158 = RES0603_0: RES, 0603 27.4k OHMS 1% 1/10W; Manufacturer: Panasonic; Manufacturer P/N: ERJ-3EKF2002V; Part Number: VISHAY CRCW060327K4FKEA; Vendor: Digikey; Vendor P/N: P20.0KHCT-ND; Volts/Amps/Watts: 0.1W
R159 = RES0603_0: RES, 0603 226K OHMS 1% 1/10W; Component: res; Label: <label>; Manufacturer: Panasonic; Manufacturer P/N: ERJ-3EKF5901V; Part Number: VISHAY CRCW0603226KFKEA; Tolerance: 1%; Vendor: Digikey; Vendor P/N: P5.90KHCT-ND; Volts/Amps/Watts: 0.1W
R160 = POT: RES, VARIABLE 5K; Part Number: BOURNS 3386P-1-502-LF
R161 = RES0603_0: RES, 0603 20K OHMS 5% 1/10W; Manufacturer: Panasonic; Manufacturer P/N: ERJ-3EKF2002V; Part Number: VISHAY CRCW060320K0JNEA; Vendor: Digikey; Vendor P/N: P20.0KHCT-ND; Volts/Amps/Watts: 0.1W
R162 = RES2512_0: RES, 1206 0 OHMS JUMPER; Component: res; Manufacturer: Panasonic; Manufacturer P/N: ERJ-M1WSF8M0U; Part Number: VISHAY CRCW12060000Z0EA; Tolerance: 1%; Vendor: Digikey; Vendor P/N: ERJ-M1WTF2M0U; Volts/Amps/watts: 1W
R163 = RES2512_0: RES, 1206 0 OHMS JUMPER OPTION; Component: res; Manufacturer: Panasonic; Manufacturer P/N: ERJ-M1WSF8M0U; Part Number: VISHAY CRCW12060000Z0EA OPTION; Tolerance: 1%; Vendor: Digikey; Vendor P/N: ERJ-M1WTF2M0U; Volts/Amps/watts: 1W
R170 = RES0603_0: RES, 0603 340 OHMS 1% 1/10W; Manufacturer: ROHM; Manufacturer P/N: MCR03EZPFX4991; Part Number: VISHAY CRCW0603340RFKEA; Vendor: Digikey; Vendor P/N: RHM4.99KHCT-ND; Volts/Amps/Watts: 0.1w
U3 = LT3685EMSE_0: IC, SYNCHRONUS STEP-DOWN CONVERTER; Part Number: LINEAR TECH. LTC3630EMSE#PBF
U5 = LT1129CS8-3_1.3: IC, LTC6992; Part Number: LINEAR TECH. LTC6992IS6-1
U6 = LT1129CS8-3_2.3: IC, SINGLE OP AMP; Part Number: LINEAR TECH. LT1803IS5
XJP1-XJP3 XJP5 XJP6 = Samtec_2SN-BK-G_5: SHUNT; Part Number: SAMTEC 2SN-BK-G
C82 C83 = CAP_NP: CAP, 0603 10nF 10% 25V X7R; Part Number: AVX 06033C103KAT2A
D9 D12 = DIODE_SCHOTTKY_9: DIODE, OPTION; Part Number: OPTION
E23-E27 E29 E30 E32 = E_0: TURRET; Part Number: MILL-MAX 2501-2-00-80-00-00-07-0
J9 = PMBUS_HEADER20_3: HEADER, 14PIN DUAL ROW R/A; Component: con; Manufacturer: Mill Max; Manufacturer P/N: 802-40-020-20-0001; Part Number: MOLEX 87760-1416; Part Type: HDR_2X10_RA_REV; Type: header RA 20 dual row; Vendor: LTC; Vendor P/N: 802-40-020-20-001
J10 = PMBUS_CONNECTOR20_3: CONN, SOCKET 14PIN  DUAL ROW R/A; Component: con; Manufacturer: Mill Max; Manufacturer P/N: 803-93-020-20-001; Part Number: SULLINSINC. NPPN072FJFN-RC; Part Type: HDR2X10RA; Type: conn  RA 20 dual row; Vendor: LTC; Vendor P/N: 803-93-020-20-001
J11 = HD2X6-079-PMBUS_2: HEADER, 12PIN 2mm STR DL; Label: DC1427A HEADER; Manufacturer: MOLEX; Manufacturer P/N: 87831-1220; Part Number: FCI 98414-G06-12ULF; Type: header 12POS 2MM VERT; Vendor: Digikey; Vendor P/N: WM18561-ND
JP2 JP3 = Samtec_TMM-103-02-L-S_0: HEADER, 3 PIN 2mm; 10th Part Field: ITH; 11th Part Field: C; 12th Part Field: RUN1; 9th Part Field: NC; Part Number: SULLINS NRPN031PAEN-RC
R102-R105 R108 R110 R111 R117 = RES0603_0: RES, 0603 OPTION; Label: OPT 0; Manufacturer: Rohm; Manufacturer P/N: RHM0.0GCT-ND; Part Number: OPTION; Tolerance: 5%; Vendor: Digikey; Vendor P/N: RHM0.0GCT-ND; Volts/Amps/Watts: 0.1W
R106 = RES0603_0: RES, 0603 0 OHMS JUMPER; Label: OPT 0; Manufacturer: Rohm; Manufacturer P/N: RHM0.0GCT-ND; Part Number: VISHAY CRCW06030000Z0EA; Tolerance: 5%; Vendor: Digikey; Vendor P/N: RHM0.0GCT-ND; Volts/Amps/Watts: 0.1W
R107 = RES0603_3: RES, 1206 OPTION; Label: OPT 0; Manufacturer: Rohm; Manufacturer P/N: RHM0.0GCT-ND; Part Number: OPTION; Tolerance: 5%; Vendor: Digikey; Vendor P/N: RHM0.0GCT-ND; Volts/Amps/Watts: 0.1W
R109 = RES0603_0: RES, 0603 0 OHMS JUMPER; Manufacturer: Rohm; Manufacturer P/N: RHM0.0GCT-ND; Part Number: VISHAY CRCW06030000Z0EA; Tolerance: 5%; Vendor: Digikey; Vendor P/N: RHM0.0GCT-ND; Volts/Amps/Watts: 0.1W
R114 R115 = RES0603_1: RES, 0603 10 OHMS 5% 1/10W; Manufacturer: Rohm; Manufacturer P/N: RHM0.0GCT-ND; Part Number: VISHAY CRCW060310R0JNEA; Tolerance: 5%; Vendor: Digikey; Vendor P/N: RHM0.0GCT-ND; Volts/Amps/Watts: 0.1W
R116 = RES0603_3: RES, 0603 OPTION; Label: OPT 0; Manufacturer: Rohm; Manufacturer P/N: RHM0.0GCT-ND; Part Number: OPTION; Tolerance: 5%; Vendor: Digikey; Vendor P/N: RHM0.0GCT-ND; Volts/Amps/Watts: 0.1W
R119 R120 = RES0603_0: RES, 0603 4.99K OHMS 1% 1/10W; Manufacturer: ROHM; Manufacturer P/N: MCR03EZPFX4991; Part Number: VISHAY CRCW06034K99FKEA; Vendor: Digikey; Vendor P/N: RHM4.99KHCT-ND; Volts/Amps/Watts: 0.1w
SW1 SW2 = JP3X1_079_NO_12_3: SWITCH, SUBMINATURE SLIDE; Part Number: C&K JS202011CQN
U4 = 24LC025-I_SN: IC, 24LC05-I/ST; Part Number: MICROCHIP 24LC025-I/ST

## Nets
3V3: J11.5(LGKPWR) Q20.2(S) Q27.3(D) Q28.2(S) Q29.2(S) R87.1 R88.1 R108.1
+5V: C101.1 C102.2 JP6.1 JP6.2 R151.1 U5.5(V+) U6.5(V+)
GND_POWER: C1.2 C3.1 C7.2 C8.2 C10.2 C11.2 C12.2 C14.2 C15.2 C16.2 C17.2 C21.2 C22.2 C24.2 C25.2 C26.2 C29.2 C30.2 C31.2 C32.2 C37.1 C38.1 C39.1 C40.1 C70.2 C71.1 C72.2 C74.2 C75.2 C76.2 C77.1 C79.2 C80.2 C81.2 C82.2 C83.2 C84.2 C85.2 C86.2 C87.2 C88.2 C93.2 C94.2 C95.2 C96.2 C97.2 C101.2 C102.1 C103.2 D8.2(ANODE) D15.2(A) E1.1(A) E4.1(A) E8.1(A) E18.1(A) E21.1(A) J2.1 J4.1 J6.1 J7.2 J7.3 J7.4 J7.5 J9.11(GND) J9.12(GND) J10.11(GND) J10.12(GND) J11.3(GND) J11.10(GND) J12.2 J12.3 J12.4 J12.5 JP1.3 Q3.1(S) Q3.2(S) Q3.3(S) Q4.1(S) Q4.2(S) Q4.3(S) Q7.1(S) Q7.2(S) Q7.3(S) Q8.1(S) Q8.2(S) Q8.3(S) Q22.2(S) Q23.2(S) R27.1 R89.2 R91.1 R93.2 R97.2 R99.1 R132.2 R145.2 R146.2 R147.2 R152.2 R158.1 R160.1(A) R160.2(WIPER) R170.2 R171.2 R172.2 SW1.3 SW2.3 U3.8(GND) U3.14(GND) U3.16(GND) U3.17(GND) U4.1(A0) U4.2(A1) U4.3(A2) U4.4(VSS) U4.7(WP) U5.2(GND) U6.2(V-)
GND_SIGNAL: C18.2 C20.2 C27.2 C33.2 C34.2 C36.2 E32.1(A) Q9.1(BASE) Q9.3(COLLECTOR) Q10.1(BASE) Q10.3(COLLECTOR) R30.1 R32.1 R34.1 R36.1 R40.1 R46.1 R49.1 U1.53(GND_SIGNAL)
VDD25: C37.2 E38.1(A) R31.2 R33.2 R35.2 R39.2 R41.2 R48.2 U1.27(VDD25)
VDD33: C38.2 E37.1(A) Q27.2(S) R10.2 R11.2 R13.2 R15.2 R16.2 R18.2 R23.2 R25.2 R28.2 R29.2 R112.1 R113.1 U1.30(VDD33)
VIN: C1.1 C74.1 C78.1 C85.1 C86.1 C87.1 C94.1 C95.1 E3.1(A) J1.1 R2.2 R3.1 R9.1 R100.1 R101.1 R107.1 R122.2 R144.1 U3.3(VIN)
VIN_PWR: C7.1 C8.1 C21.1 C22.1 C96.1 C97.1 Q1.5(D) Q2.5(D) Q5.5(D) Q6.5(D) R2.1 R4.1 R122.1
ALERTB: E23.1(A) J9.3(ALERTB) J10.3(ALERTB) J11.6(ALERTB) Q20.1(G) R15.1 U1.16(~{ALERTB})
AUXVCC: C84.1 J9.8(AUXP) J10.8(AUXP) J11.1(AUXP) R119.1 R120.1 U4.8(VCC)
BG0: Q3.4(G) Q4.4(G) U1.50(BG0)
BG1: Q7.4(G) Q8.4(G) U1.42(BG1)
BOOST0: R12.2 U1.52(BOOST0)
BOOST1: R38.2 U1.40(BOOST1)
DRVCC: C39.2 D1.2(A) D2.2(A) E2.1(A) U1.44(DRVCC)
EESCL: J11.11(AUXSCL) R119.2 U4.6(SCL)
EESDA: J11.12(AUXSDA) R120.2 U4.5(SDA)
EXT_SUPPLY: C73.1 C75.1 C76.1 C79.1 C80.1 E39.1(A) JP6.3 L5.2 R96.1 R174.2
EXTVCC: C40.2 D15.1(K) E20.1(A) R168.2 R169.2 R174.1 U1.43(EXTVCC)
FAULT0B: D12.2(ANODE) E11.1(A) JP2.1 JP2.2 Q29.1(G) R18.1 R104.2 R105.2 U1.17(\\~{FAULT}0)
FAULT1B: D9.2(ANODE) E22.1(A) JP2.3 Q28.1(G) R23.1 R102.2 R103.2 U1.18(\\~{FAULT}1)
ISENSE0+: C13.1 R24.2 U1.4(ISENSE0+)
ISENSE0-: C13.2 C19.1 R26.2 U1.5(ISENSE0-)
ISENSE1+: C28.1 R50.1 U1.9(ISENSE1+)
ISENSE1-: C28.2 C35.1 R51.1 U1.10(ISENSE1-)
ITH0: C20.1 R118.1 U1.12(ITH0)
ITH1: C36.1 R118.2 U1.31(ITH1)
ITHR0: C18.1 R173.2 U1.11(ITHR0)
ITHR1: C34.1 R173.1 U1.32(ITHR1)
PG0: E35.1(A) Q23.1(G) R25.1 R148.1 U1.34(PGOOD0)
PG1: E36.1(A) Q22.1(G) R28.1 R148.2 U1.33(PGOOD1)
RUN0: D12.1(CATHODE) E29.1(A) JP3.3 R103.1 R106.2 R113.2 R115.2 SW1.1 SW1.2 U1.19(RUN0)
RUN1: D9.1(CATHODE) E30.1(A) JP3.1 JP3.2 R105.1 R111.2 R112.2 R114.2 SW2.1 SW2.2 U1.20(RUN1)
SCL: E25.1(A) J9.6(SCL) J10.6(SCL) J11.4(SCL) R11.1 U1.14(SCL)
SDA: E24.1(A) J9.4(SDA) J10.4(SDA) J11.2(SDA) R13.1 U1.15(SDA)
SHARE_CLK: E26.1(A) R16.1 R109.1 U1.29(SHARE_CLK)
SW0: C9.2 L1.1 L7.1 Q1.1(S) Q1.2(S) Q1.3(S) Q2.1(S) Q2.2(S) Q2.3(S) Q3.5(D) Q4.5(D) R19.1 R90.2 U1.1(SW0)
SW0A: L1.2 L7.2 R14.1 R20.1 R21.1
SW1: C23.2 L2.2 L9.2 Q5.1(S) Q5.2(S) Q5.3(S) Q6.1(S) Q6.2(S) Q6.3(S) Q7.5(D) Q8.5(D) R42.1 R92.2 U1.39(SW1)
SW1A: L2.1 L9.1 R37.1 R44.1 R47.2
SYNC: E27.1(A) R10.1 R110.1 U1.13(SYNC)
TG0: R128.1 U1.2(TG0)
TG1: R129.1 U1.38(TG1)
TSNS0: C27.1 Q9.2(EMITTER) U1.6(TSNS0)
TSNS1: C33.1 Q10.2(EMITTER) U1.36(TSNS1)
VOUT0: C10.1 C11.1 C12.1 C14.1 C15.1 C16.1 C17.1 C70.1 C88.1 J3.1 J7.1 R5.2 R6.2 R7.2 R8.2 R14.2 R17.1 R22.1 R162.1 R168.1
VOUT1: C24.1 C25.1 C26.1 C29.1 C30.1 C31.1 C32.1 C93.1 C103.1 J5.1 J12.1 R5.1 R6.1 R7.1 R8.1 R37.2 R43.1 R45.1 R163.1 R169.1
VSENSE0+: E5.1(A) R17.2 R121.1 U1.7(VSENSE0+)
VSENSE0-: E6.1(A) R27.2 U1.8(VSENSE0-)
VSENSE1: E7.1(A) R45.2 R121.2 U1.35(VSENSE1+)
WP: R29.1 R30.2 U1.28(WP)
N20549080: J11.8(OUTEN_0) R116.1
N20549082: J11.9(OUTEN_1) R117.1
N20549096: J9.2(CTRL) J10.2(CTRL) R106.1 R111.1 R116.2 R117.2
N20549100: J9.13(12V) J9.14(12V) J10.13(12V) J10.14(12V) R107.2
N20549243: C82.1 R114.1
N20549256: J9.10(UNUSED) J10.10(UNUSED) R108.2
N20549273: C83.1 R115.1
N20549287: J9.5(SHARE_CLK) J10.5(SHARE_CLK) R109.2
N20549363: J9.9(UNUSED) J10.9(UNUSED) R110.2
N20549437: J9.1(FAULTB) J10.1(FAULTB) R102.1 R104.1
N20549487: J9.7(RESETB) J10.7(RESETB)
N20554796: R41.1 R46.2 U1.25(FREQ_CFG)
N20554918: R48.1 R49.2 U1.26(PHAS_CFG)
N20554976: C35.2 R43.2 R47.1 R51.2
N20555079: C9.1 D1.1(K) R12.1
N20555212: C77.2 R92.1
N20555214: Q1.4(G) Q2.4(G) R128.2
N20555355: Q5.4(G) Q6.4(G) R129.2
N20555456: R42.2 R44.2 R50.2
N20555530: C23.1 D2.1(K) R38.1
N20555594: C5.2 C6.1 R4.2 U1.46(IIN-)
N20555669: C4.2 C6.2 R3.2 U1.47(IIN+)
N20555715: C71.2 R90.1
N20555854: R31.1 R32.2 U1.21(ASEL0)
N20555893: C3.2 C4.1 C5.1 R9.2 U1.48(VIN)
N20556038: C19.2 R20.2 R22.2 R26.1
N20556154: R33.1 R34.2 U1.22(ASEL1)
N20556179: R35.1 R36.2 U1.23(VOUT0_CFG)
N20556187: R39.1 R40.2 U1.24(VOUT1_CFG)
N20556217: R19.2 R21.2 R24.1
N20562366: JP5.1 R153.2
N20562368: JP5.2 JP5.3 Q19.4(G) R89.1 R157.2
N20562376: E16.1(A) Q19.1(S) Q19.2(S) Q19.3(S) R91.2 R154.2
N20562382: E14.1(A) R157.1
N20562418: Q19.5(D) R162.2 R163.2
N20562513: C73.2 R96.2 R97.1 U3.9(VFB)
N20562533: R98.1 U3.7(VPRG1)
N20562535: R132.1 U3.6(VPRG2)
N20562544: C72.1 R98.2 U3.10(SS)
N20562801: L5.1 U3.1(SW)
N20562899: JP1.2 U3.5(RUN)
N20562907: C78.2 R146.1
N20563002: D8.1(CATHODE) JP1.1 R100.2 R147.1
N20563074: C81.1 R99.2 R101.2 U3.11(ISET)
N20563129: C100.2 R153.1 U6.1(VOUT)
N20563131: R155.1 R161.1 U6.3(+IN)
N20563149: R151.2 R152.1 U5.4(DIV)
N20563171: R161.2 U5.6(OUT)
N20563173: R155.2 R160.3(B) R170.1
N20563252: R158.2 R159.1 U5.1(MOD)
N20563280: C100.1 R154.1 U6.4(-IN)
N20563334: R159.2 U5.3(SET)
N20563414: Q27.1(G) R144.2 R145.1
N20563495: D6.2(A) R87.2
N20563497: D6.1(K) Q23.3(D)
N20563528: D5.1(K) Q22.3(D)
N20563532: D7.2(A) Q20.3(D)
N20563579: D5.2(A) R88.2
N20563596: D7.1(K) R93.1
N20671975: D14.2(A) Q29.3(D)
N20671988: D14.1(K) R172.1
N20672153: D13.2(A) Q28.3(D)
N20672166: D13.1(K) R171.1

Not connected (* = marked no-connect by the designer): J11 7(GPIO_1); SW1 4 5 6; SW2 4 5 6; U1 3(NC) 37(NC) 41(NC) 45(NC) 49(NC) 51(NC); U3 12(FBO)*

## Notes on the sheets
sheet 1
- Optional Resistors for Single Output Configuration
- 2
- 2
- 2
- 2
- 2
- 2
- 2
- 2
- 2m
- 2010
- 63V
- OPT
- OPT
- 0
- 0
- 100
- 1nF
- 100
- OS-CON
- OS-CON
- 7343
- OPT
- 7343
- OPT
- 50V
- 50V
- OPT
- 2m
- 2010
- 63V
- 63V
- OPT
- OPT
- 0
- 0
- 100
- 1nF
- 100
- 7343
- OS-CON
- OS-CON
- 7343
- OPT
- OPT
- 50V
- 50V
- OPT
- NOTE: UNLESS OTHERWISE SPECIFIED
- 1.  ALL RESISTORS AND CAPACITORS ARE 0603.
- 2   FOR SINGLE OUTPUT CONFIGURATION.
- NOTE:
  T1 - T8 ARE EXPOSED PCB VIAS
  FOR USE AS TEST POINTS
- NOTE:
  VOUT0 AND VOUT1 DEFAULT OUTPUT = 1.8V
- LTC3880EUJ - CURRENT MODE DUAL PHASE / DUAL CHANNEL
  STEP-DOWN CONTROLLER WITH I2C / PMBus INTERFACE
- MAKE ALL SENSE CONNECTIONS TO L1/L2
  AND R10/R16 DIFFERENTIAL AND KELVIN
sheet 2
- ALL PARTS ON THIS PAGE ARE FOR DEMO ONLY, NOT NEEDED IN CUSTOMER DESIGN
- DYNAMIC LOAD CIRCUIT
- DO NOT EXCEED 5% DUTY CYCLE!
- 48Hz,
- Less Than 3% Duty Cycle
- NOTE:
  PULSE OUT
  10mV / AMP
- VOUT0
- VOUT1
- PG0
- PG1
- 5.5V
- ALERTB
- FAULT0B
- FAULT1B
sheet 3
- ALL PARTS ON THIS PAGE ARE FOR DEMO ONLY, NOT NEEDED IN CUSTOMER DESIGN
- FAULT0B-FAULT1B
- RUN0-RUN1
- TO DC1613A
- RUN1
- RUN0
- ON
- ON
- OFF
- OFF
